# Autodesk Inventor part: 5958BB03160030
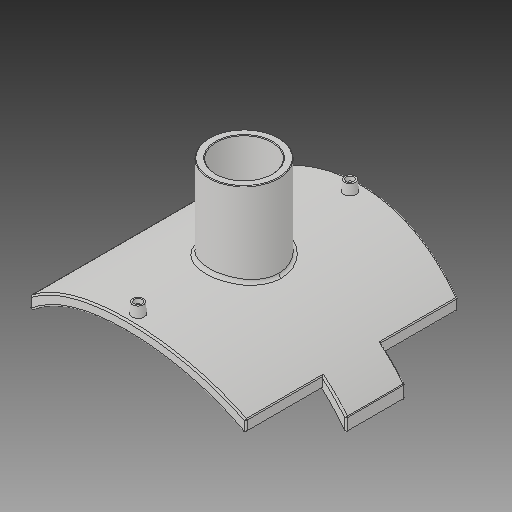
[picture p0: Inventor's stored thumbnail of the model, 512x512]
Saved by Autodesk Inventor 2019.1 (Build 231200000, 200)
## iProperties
Created: 2017-10
Part Number: 5958BB03160030
Material: Generic
Description: PLASSON BRANCH SADDLE 10''-16''IPS x 10''-14''DIPS
Document SubType Name: Modeling
Designer: KIM
Density: 1 g/cm^3
Appearance: Default
Author: KIM
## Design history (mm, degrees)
derived "5958B-1.ipt"
feature "Solid1::5958B-1.ipt"
tag "TaggingFeature1"
body "Solid1"
other parameters: "d0" = 404.6, "d1" = 12.954, "d2" = 274.32, "d3" = 299.974, "d4" = 0, "d5" = 304.8, "d6" = 74.9935, "d7" = 0, "d8" = 134.9883, "d10" = 0, "d11" = 2.023, "d12" = 227.9, "d13" = 14, "d14" = 134.9883, "d16" = 5 deg, "d18" = 4, "d19" = 14, "d20" = 0, "d21" = 3, "d22" = 0, "d23" = 319.14, "d24" = 88.7, "d25" = 16, "d26" = 70.96, "d28" = 0, "d29" = 9.6, "d31" = 0, "d32" = 81.788, "d33" = 0, "d34" = 4.046, "d35" = 0.8092, "d_" = 404.6, "d_1" = 88.7, "B_" = 304.8, "H_" = 116.84, "L_" = 299.974, "x_" = 12.954, "D_" = 16, "H1" = 103.886
